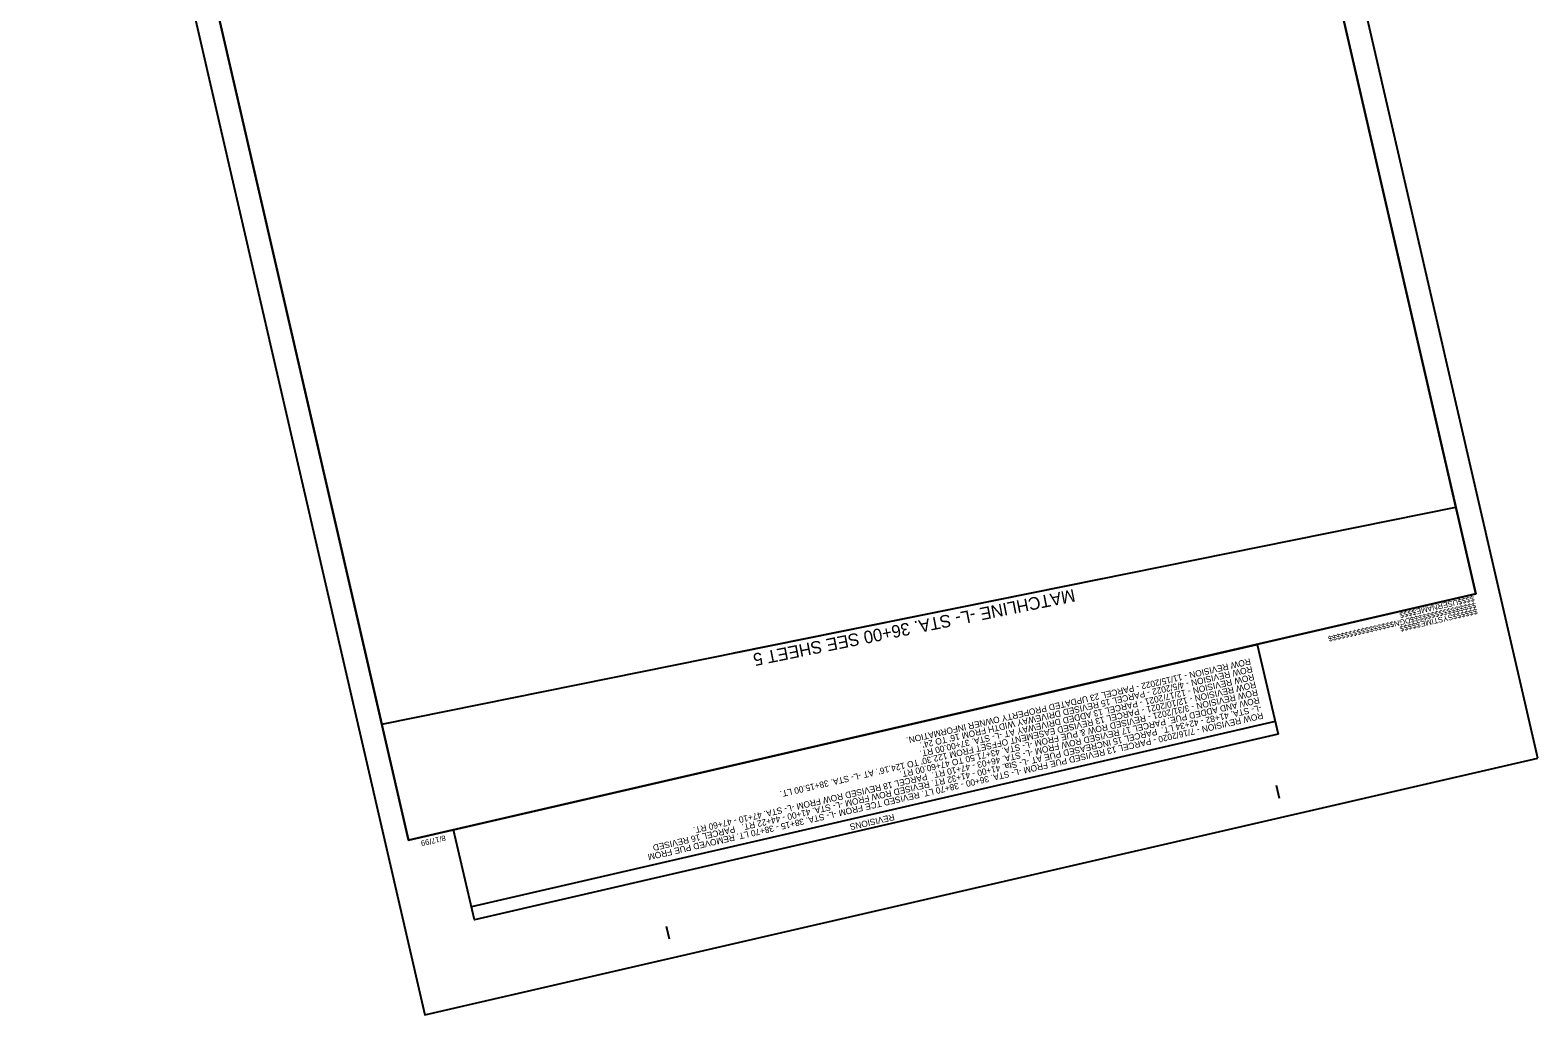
# Model space of a CAD drawing. Extents: x 480532 to 481977, y 491295 to 493182.
# Drawn here: x 480532 to 481977, y 491295 to 492238 of the extents above; entities that cross this region are included whole.
import ezdxf

# ---------------------------------------------------------------- set-up
doc = ezdxf.new("R2010")
doc.units = 0
for name, color, linetype in [('Matchline', 7, 'Continuous'), ('Matchline Text', 7, 'Continuous'), ('Sheet Block Revision CELL', 7, 'Continuous'), ('Sheet Clip Boundary CELL', 7, 'Continuous'), ('Sheet Plan CELL', 7, 'Continuous'), ('Sheet Plot Border Outside CELL', 7, 'Continuous')]:
    doc.layers.add(name, color=color, linetype=linetype)

msp = doc.modelspace()

# ---------------------------------------------------------------- linework, layer by layer
at = {"layer": 'Matchline'}
msp.add_line((481207.2, 491641.8), (481560.1, 491713), dxfattribs=at)
at = {"layer": 'Sheet Block Revision CELL'}
msp.add_line((481725.6, 491576.1), (480955.2, 491398.5), dxfattribs=at)
msp.add_lwpolyline([(481728.4, 491563.9), (480958, 491386.3), (480938.1, 491472.4), (481708.5, 491650)], close=True, dxfattribs=at)
at = {"layer": 'Sheet Clip Boundary CELL'}
msp.add_lwpolyline([(481665.8, 492792.6), (481626.6, 492783.6), (481580.2, 492984.7), (481541.5, 492975.8), (481503.1, 493142), (481251.1, 493083.9), (481239.4, 493081.2), (480865.4, 492806.9), (480812.7, 492777.4), (480745.4, 492725.1), (480625.3, 492632), (480625.3, 492632), (480625.3, 492632), (480625.3, 492632), (480625.3, 492632), (480869.3, 491573.6), (481898.9, 491781.4)], close=True, dxfattribs=at)
at = {"layer": 'Sheet Plan CELL'}
for p, q in [((481918.1, 491698.3), (481918.1, 491698.3)), ((481729.7, 491502.5), (481726.9, 491514.7)), ((480894.9, 491462.4), (480894.9, 491462.4)), ((481145.1, 491367.7), (481142.3, 491379.9))]:
    msp.add_line(p, q, dxfattribs=at)
for points in [[(480557.9, 492924.1), (480894.9, 491462.4), (481918.1, 491698.3), (481581.1, 493160)], [(481918.1, 491698.3), (480894.9, 491462.4), (480602.9, 492729.2), (480749.1, 492762.9), (480704.2, 492957.8), (481581.1, 493160)]]:
    msp.add_lwpolyline(points, close=True, dxfattribs=at)
at = {"layer": 'Sheet Plot Border Outside CELL'}
msp.add_lwpolyline([(481977.4, 491541.1), (481599.2, 493181.6), (480532.2, 492935.6), (480910.4, 491295.2)], close=True, dxfattribs=at)

# ---------------------------------------------------------------- texts
at = {"layer": 'Matchline Text'}
msp.add_text('MATCHLINE -L- STA. 36+00 SEE SHEET 5', height=12, rotation=191.4142, dxfattribs=at).set_placement((481532.5, 491703.1))
at = {"layer": 'Sheet Block Revision CELL'}
for s, p in [('ROW REVISION - 11/15/2022 - PARCEL 23 UPDATED PROPERTY OWNER INFORMATION. ', (481701.4, 491636.8)), ('ROW REVISION - 12/17/2021 - PARCEL 13 ADDED DRIVEWAY AT -L- STA. 37+00.00 RT. ', (481704.8, 491621.9)), ("ROW REVISION - 4/5/2022 - PARCEL 15 REVISED DRIVEWAY WIDTH FROM 16' TO 24'. ", (481703.1, 491629.4)), ("ROW REVISION - 12/10/2021 - PARCEL 13 REVISED EASEMENT OFFSET FROM 122.30' TO 124.16'. AT -L- STA. 38+15.00 LT. ", (481706.5, 491614.5)), ('ROW AND ADDED PUE. PARCEL 17 REVISED ROW FROM -L- STA. 46+03 - 47+10 RT.  PARCEL 18 REVISED ROW FROM -L- STA. 47+10 - 47+60 RT.', (481709.9, 491599.7)), ('ROW REVISION - 3/31/2021 - REVISED ROW & PUE FROM -L- STA. 43+71.50 TO 47+60.00 RT.', (481708.2, 491607.1)), ('ROW REVISION - 7/16/2020 - PARCEL 13 REVISED PUE FROM -L- STA. 36+00 - 38+70 LT. REVISED TCE FROM -L- STA. 38+15 - 38+70 LT. REMOVED PUE FROM', (481713.4, 491584.9)), ('-L- STA. 41+82 - 42+34 LT.  PARCEL 15 INCREASED PUE AT -L- Sta. 41+00 - 41+32 RT. REVISED ROW FROM -L- STA. 41+00 - 44+22 RT.   PARCEL 16 REVISED', (481711.7, 491592.3)), ('REVISIONS', (481360, 491487.7))]:
    msp.add_text(s, height=6, rotation=192.9811, dxfattribs=at).set_placement(p)
at = {"layer": 'Sheet Plan CELL'}
for s, p in [('$$$$USERNAME$$$$', (481916, 491696.7)), ('$$$$$$$$$$$$$$$$DGN$$$$$$$$$$$$$$$$', (481917.5, 491690.3)), ('$$$$$$SYSTIME$$$$$', (481918.9, 491684.4)), ('8/17/99', (480929.9, 491467.2))]:
    msp.add_text(s, height=5.25, rotation=192.9811, dxfattribs=at).set_placement(p)

doc.saveas('drawing.dxf')
